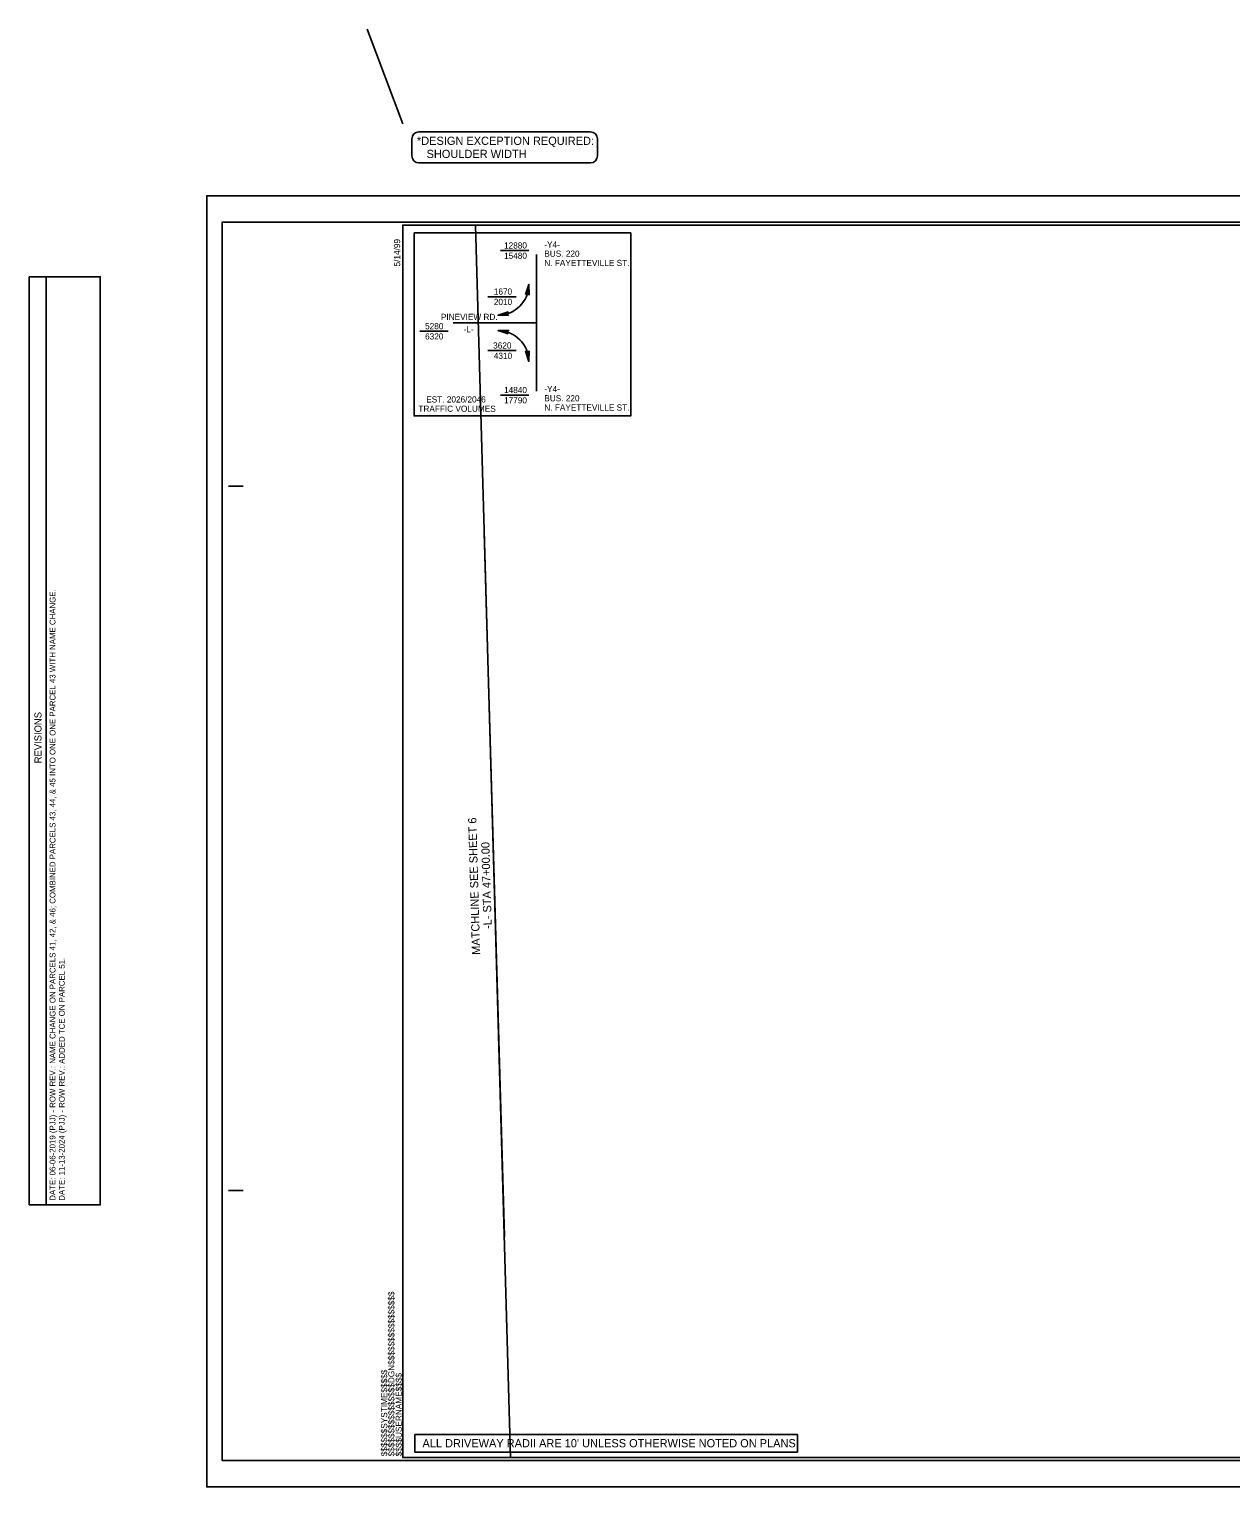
# Model space of a CAD drawing. Extents: x 1758987 to 1761034, y 736518 to 737760.
# Drawn here: x 1758987 to 1760011, y 736518 to 737760 of the extents above; entities that cross this region are included whole.
import ezdxf

# ---------------------------------------------------------------- set-up
doc = ezdxf.new("R2010")
doc.units = 0
for name, color, linetype in [('Matchline', 7, 'Continuous'), ('Matchline Text', 7, 'Continuous'), ('Old_Level_18', 7, 'Continuous'), ('Old_Level_38', 7, 'Continuous'), ('Old_Level_42', 7, 'Continuous'), ('Prop DSN Text', 7, 'Continuous'), ('Prop Grid Mask', 7, 'Continuous'), ('Prop Horizontal Alignment', 7, 'Continuous'), ('Prop Terminator CELL', 7, 'Continuous'), ('Sheet Block Revision CELL', 7, 'Continuous'), ('Sheet Border Standard 30in CELL', 7, 'Continuous'), ('Sheet Clip Boundary CELL', 7, 'Continuous'), ('Sheet Cutting Line CELL', 7, 'Continuous'), ('Sheet Plot Border Inside CELL', 7, 'Continuous'), ('Sheet Plot Border Outside CELL', 7, 'Continuous')]:
    doc.layers.add(name, color=color, linetype=linetype)

msp = doc.modelspace()

# ---------------------------------------------------------------- linework, layer by layer
at = {"layer": 'Matchline'}
msp.add_line((1759374.5, 737330.7), (1759391.6, 736730.9), dxfattribs=at)
at = {"layer": 'Old_Level_18'}
for p, q in [((1759318.8, 737672.2), (1759464.9, 737672.2)), ((1759312.8, 737666.2), (1759312.8, 737651.7)), ((1759470.9, 737666.2), (1759470.9, 737651.7)), ((1759318.8, 737645.7), (1759464.9, 737645.7))]:
    msp.add_line(p, q, dxfattribs=at)
for centre, start, end in [((1759318.8, 737666.2), 90, 180), ((1759464.9, 737666.2), 0, 90), ((1759318.8, 737651.7), 180, 270), ((1759464.9, 737651.7), 270, 0)]:
    msp.add_arc(centre, 6, start, end, dxfattribs=at)
at = {"layer": 'Old_Level_42'}
msp.add_line((1759305, 737679), (1759274.7, 737759.7), dxfattribs=at)
at = {"layer": 'Prop DSN Text'}
for p, q in [((1759388.3, 737571), (1759412.5, 737571)), ((1759377.6, 737531.7), (1759401.7, 737531.7)), ((1759319.6, 737502.3), (1759343.8, 737502.3)), ((1759377.6, 737485.8), (1759401.7, 737485.8)), ((1759388.3, 737447.9), (1759412.5, 737447.9))]:
    msp.add_line(p, q, dxfattribs=at)
at = {"layer": 'Prop Grid Mask'}
msp.add_lwpolyline([(1759315.2, 736562.4), (1759641.2, 736562.4), (1759641.2, 736547.4), (1759315.2, 736547.4)], close=True, dxfattribs=at)
at = {"layer": 'Prop Horizontal Alignment'}
for p, q in [((1759419, 737567.7), (1759419, 737509.4)), ((1759419, 737509.4), (1759347.9, 737509.4)), ((1759419, 737509.4), (1759419, 737451.2))]:
    msp.add_line(p, q, dxfattribs=at)
msp.add_lwpolyline([(1759314.6, 737586.1), (1759499.2, 737586.1), (1759499.2, 737430.2), (1759314.6, 737430.2)], close=True, dxfattribs=at)
for centre, start, end in [((1759386.2, 737542.2), 270, 0), ((1759386.2, 737476.6), 0, 90)]:
    msp.add_arc(centre, 26.2, start, end, dxfattribs=at)
at = {"layer": 'Prop Terminator CELL'}
for points in [[(1759409.6, 737533.7), (1759412.5, 737542.2), (1759412.7, 737533.2), (1759411.3, 737534.6)], [(1759395.2, 737515.7), (1759386.2, 737516), (1759394.8, 737518.8), (1759393.9, 737517.1)], [(1759394.7, 737500), (1759386.2, 737502.9), (1759395.3, 737503), (1759393.9, 737501.6)], [(1759412.7, 737485.6), (1759412.5, 737476.6), (1759409.6, 737485.2), (1759411.3, 737484.3)]]:
    msp.add_lwpolyline(points, close=True, dxfattribs=at)
at = {"layer": 'Sheet Block Revision CELL'}
msp.add_line((1759001.2, 736758), (1759001.2, 737548.6), dxfattribs=at)
msp.add_lwpolyline([(1758986.7, 736758), (1758986.7, 737548.6), (1759047.2, 737548.7), (1759047.2, 736758)], close=True, dxfattribs=at)
at = {"layer": 'Sheet Border Standard 30in CELL'}
for p, q in [((1759306, 737592.7), (1759306, 737592.7)), ((1759156.5, 737370.2), (1759169, 737370.2)), ((1759156.5, 736770.2), (1759169, 736770.2))]:
    msp.add_line(p, q, dxfattribs=at)
msp.add_lwpolyline([(1760805, 737592.7), (1759305, 737592.7), (1759305, 736542.7), (1760805, 736542.7)], close=True, dxfattribs=at)
at = {"layer": 'Sheet Clip Boundary CELL'}
msp.add_lwpolyline([(1759396.9, 736542.7), (1760805, 736542.7), (1760805, 737347.1), (1760605, 737347.1), (1760605, 737592.7), (1759367.1, 737592.7)], close=True, dxfattribs=at)
msp.add_lwpolyline([(1759396.9, 736542.7), (1760805, 736542.7), (1760805, 737347.1), (1760605, 737347.1), (1760605, 737592.7), (1759367.1, 737592.7)], close=True, dxfattribs=at)
at = {"layer": 'Sheet Cutting Line CELL'}
for p, q in [((1760822, 737617.7), (1759138, 737617.7)), ((1759138, 737617.7), (1759138, 736517.7)), ((1759138, 736517.7), (1760822, 736517.7))]:
    msp.add_line(p, q, dxfattribs=at)
at = {"layer": 'Sheet Plot Border Inside CELL'}
msp.add_lwpolyline([(1760817.5, 737595.3), (1759151, 737595.3), (1759151, 736540.2), (1760817.5, 736540.2)], close=True, dxfattribs=at)
at = {"layer": 'Sheet Plot Border Outside CELL'}
msp.add_lwpolyline([(1760822, 737617.7), (1759138, 737617.7), (1759138, 736517.7), (1760822, 736517.7)], close=True, dxfattribs=at)

# ---------------------------------------------------------------- texts
at = {"layer": 'Matchline Text'}
for s, p in [('MATCHLINE SEE SHEET 6', (1759371, 736971.1)), ('-L- STA 47+00.00', (1759380.9, 736993.1))]:
    msp.add_text(s, height=7, rotation=91.6265, dxfattribs=at).set_placement(p)
at = {"layer": 'Old_Level_38'}
for s, p in [('*DESIGN EXCEPTION REQUIRED: ', (1759317.1, 737661.1)), ('SHOULDER WIDTH', (1759325.3, 737649.9))]:
    msp.add_text(s, height=7, rotation=359.995, dxfattribs=at).set_placement(p)
at = {"layer": 'Prop DSN Text'}
for s, height, rotation, p in [('12880', 5.25, 0, (1759391.3, 737572.8)), ('15480', 5.25, 0, (1759391.3, 737564)), ('1670', 5.25, 0, (1759382.6, 737533.5)), ('2010', 5.25, 0, (1759382.6, 737524.7)), ('5280', 5.25, 0, (1759324, 737504)), ('6320', 5.25, 0, (1759324, 737495.3)), ('3620', 5.25, 0, (1759382, 737487.6)), ('4310', 5.25, 0, (1759382.6, 737478.8)), ('EST. 2026/2046', 5.25, 0, (1759325, 737441.6)), ('14840', 5.25, 0, (1759391.3, 737449.6)), ('17790', 5.25, 0, (1759391.3, 737440.9)), ('TRAFFIC VOLUMES', 5.25, 0, (1759318.3, 737433.7)), ("ALL DRIVEWAY RADII ARE 10' UNLESS OTHERWISE NOTED ON PLANS.", 7, 359.9997, (1759321.8, 736551.4))]:
    msp.add_text(s, height=height, rotation=rotation, dxfattribs=at).set_placement(p)
at = {"layer": 'Prop Horizontal Alignment'}
for s, p in [('-Y4-', (1759425.6, 737573.6)), ('BUS. 220', (1759425.6, 737565.8)), ('N. FAYETTEVILLE ST.', (1759425.6, 737557.9)), ('PINEVIEW RD.', (1759337.5, 737511.9)), ('-L-', (1759356.8, 737501.4)), ('-Y4-', (1759425.6, 737450.5)), ('BUS. 220', (1759425.6, 737442.6)), ('N. FAYETTEVILLE ST.', (1759425.6, 737434.7))]:
    msp.add_text(s, height=5.25, rotation=0, dxfattribs=at).set_placement(p)
at = {"layer": 'Sheet Block Revision CELL'}
for s, height, p in [('DATE: 06-06-2019 (PJJ) - ROW REV.: NAME CHANGE ON PARCELS 41, 42, & 46; COMBINED PARCELS 43, 44, & 45 INTO ONE ONE PARCEL 43 WITH NAME CHANGE. ', 5, (1759009.1, 736761.5)), ('REVISIONS', 6, (1758997.2, 737134.2)), ('DATE: 11-13-2024 (PJJ) - ROW REV.: ADDED TCE ON PARCEL 51. ', 5, (1759017, 736761.5))]:
    msp.add_text(s, height=height, rotation=90, dxfattribs=at).set_placement(p)
at = {"layer": 'Sheet Border Standard 30in CELL'}
for s, p in [('5/14/99', (1759302.8, 737557.5)), ('$$$$$$$$$$$$$$$$DGN$$$$$$$$$$$$$$$$', (1759297.9, 736543.6)), ('$$$$$$SYSTIME$$$$$', (1759291.8, 736543.8)), ('$$$$USERNAME$$$$', (1759304.2, 736543.7))]:
    msp.add_text(s, height=5.25, rotation=90, dxfattribs=at).set_placement(p)

doc.saveas('drawing.dxf')
